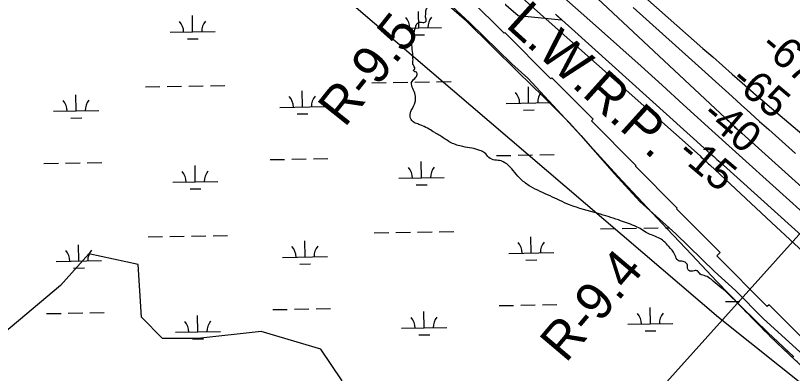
# Model space of a CAD drawing. Extents: x 3903937 to 3942190, y 260677 to 286651.
# Drawn here: x 3915846 to 3917570, y 282085 to 282879 of the extents above; entities that cross this region are included whole.
import ezdxf

# ---------------------------------------------------------------- set-up
doc = ezdxf.new("R2010")
doc.units = 0
for name, color, linetype in [('V-RIVR-EDGE', 7, 'Continuous'), ('V-RIVR-RANG', 7, 'Continuous'), ('V-RIVR-RANG-IDEN', 7, 'Continuous'), ('V-RRAP-FSHR', 7, 'Continuous'), ('V-RRAP-RVMT', 7, 'Continuous'), ('V-SITE-VEGE', 7, 'Continuous'), ('V-TOPO-DPTH', 7, 'Continuous'), ('V-TOPO-MAJR', 7, 'Continuous'), ('V-TOPO-MINR', 7, 'Continuous'), ('V-TOPO-WATR-IDEN', 7, 'Continuous'), ('V-WETL-SWMP', 7, 'Continuous')]:
    doc.layers.add(name, color=color, linetype=linetype)

msp = doc.modelspace()

# ---------------------------------------------------------------- linework, layer by layer
at = {"layer": 'V-RIVR-EDGE'}
for points in [[(3917425.1, 282263.8), (3917389, 282294.2), (3917376.9, 282301.5), (3917364.7, 282305.9), (3917358.9, 282312.7), (3917351.7, 282313.2), (3917339.5, 282313.8), (3917337.6, 282316.7), (3917335.7, 282327.9), (3917333.2, 282330.8), (3917324.5, 282334.2), (3917318.2, 282334.7), (3917313.8, 282338.1), (3917308, 282350.3), (3917295.5, 282366.8), (3917283.8, 282379), (3917272.2, 282386.3), (3917256.7, 282392.6), (3917245, 282398), (3917231.4, 282406.8), (3917219.3, 282412.6), (3917183.4, 282425.8), (3917138.3, 282440), (3917074.7, 282459.6), (3917032, 282479.1), (3916988.4, 282500.1), (3916967.5, 282515.7), (3916953.5, 282531.3), (3916939.4, 282546.9), (3916923.4, 282556.6), (3916909.4, 282558.6), (3916896.3, 282564), (3916886.6, 282574.7), (3916876.4, 282580.1), (3916858.4, 282585), (3916838.5, 282588.4), (3916812.3, 282597.2), (3916792, 282609.9), (3916782.3, 282615.7), (3916776, 282619.6), (3916763.8, 282627.4), (3916749.3, 282634.3), (3916741, 282637.7), (3916730.4, 282642.1), (3916723.6, 282648.4), (3916721.7, 282654.3), (3916721.7, 282661.1), (3916724.1, 282668.3), (3916732.9, 282687.7), (3916733.4, 282696), (3916730.5, 282710.6), (3916725.2, 282723.7), (3916724.8, 282730.5), (3916727.2, 282735.3), (3916735.5, 282744.1), (3916736.9, 282748.4), (3916736.5, 282752.3), (3916730.2, 282755.7), (3916729.2, 282758.2), (3916731.6, 282760.1), (3916731.6, 282763.5), (3916727.8, 282770.8), (3916727.3, 282772.7), (3916727.8, 282778.1), (3916727.8, 282783.9), (3916726.9, 282799), (3916725.5, 282818.4), (3916729.9, 282838.8), (3916731.4, 282846.1), (3916733.8, 282854.8), (3916737.7, 282862.1), (3916742.1, 282864.5), (3916751.8, 282863.5), (3916755.7, 282865.4), (3916757.2, 282868.8), (3916756.2, 282873.2), (3916756.2, 282883.9), (3916757.7, 282894.1), (3916764, 282902.3), (3916767, 282910.1), (3916770.4, 282913), (3916781, 282908.1), (3916789.3, 282907.6), (3916789.3, 282910), (3916782, 282918.8), (3916778.7, 282923.6), (3916763.6, 282935.3), (3916726.8, 282963.6), (3916714.2, 282972.9), (3916689, 282991.4), (3916632.3, 283034.2), (3916610, 283048.9), (3916578, 283066.9), (3916543, 283088.9), (3916510.1, 283112.7), (3916469.8, 283140.5), (3916444.2, 283160.5), (3916369, 283219), (3916281.3, 283284.2), (3916175.1, 283366.6), (3916089.8, 283429.9), (3915988, 283506.4), (3915917.7, 283560), (3915863.9, 283597.5), (3915811.6, 283639.9), (3915738.9, 283704.7)], [(3921377.3, 279062.2), (3921266.3, 279148.9), (3921205.7, 279194.7), (3921163, 279223.9), (3921117.5, 279259), (3921069, 279295.1), (3920989.5, 279356.5), (3920904.2, 279419.8), (3920848.5, 279465.1), (3920819.4, 279491.4), (3920764.6, 279532.3), (3920724.9, 279564.5), (3920717.6, 279574.2), (3920711.8, 279577.1), (3920707.9, 279580.1), (3920703.1, 279584.4), (3920697.7, 279590.3), (3920694.3, 279596.1), (3920679.8, 279608.3), (3920653.6, 279627.8), (3920647.8, 279633.1), (3920617.3, 279659.9), (3920603.2, 279669.7), (3920586.3, 279680.4), (3920572.2, 279685.8), (3920561.5, 279694.1), (3920554.7, 279695), (3920536.3, 279710.1), (3920503.8, 279735.5), (3920470.4, 279766.2), (3920409.9, 279826.5), (3920360.4, 279874.2), (3920304.2, 279925.9), (3920246.1, 279984.3), (3920184.1, 280042.2), (3920087.2, 280134.7), (3920077, 280142.5), (3920067.8, 280150.8), (3920023.2, 280189.8), (3919970.4, 280236), (3919916.1, 280284.7), (3919868.6, 280327.1), (3919856, 280338.3), (3919841, 280350), (3919835.2, 280353.4), (3919829.4, 280360.7), (3919822.1, 280368), (3919811.5, 280375.3), (3919804.7, 280378.7), (3919792.5, 280388), (3919779, 280401.1), (3919755.2, 280421.1), (3919718.9, 280448.4), (3919686.9, 280472.3), (3919581.7, 280567.7), (3919547.8, 280598.4), (3919513.9, 280625.2), (3919481.9, 280648.6), (3919448.9, 280669), (3919419.8, 280686.1), (3919392.7, 280705.6), (3919362.1, 280728), (3919330.2, 280752.9), (3919280.7, 280793.8), (3919246.8, 280820.1), (3919120.8, 280914.1), (3919044.2, 280969.7), (3918969, 281026.7), (3918955.5, 281036.9), (3918936.5, 281049.6), (3918911.8, 281069.6), (3918859, 281106.6), (3918831.8, 281126.6), (3918796, 281157.3), (3918776.6, 281169.5), (3918765, 281177.3), (3918749, 281193.3), (3918725.7, 281210.9), (3918705.3, 281225), (3918662.7, 281257.6), (3918621.5, 281285.9), (3918549.7, 281337.6), (3918525, 281357), (3918475.6, 281395.5), (3918463.5, 281407.2), (3918447, 281418.9), (3918411.1, 281449.1), (3918340.8, 281503.7), (3918290.9, 281544.1), (3918205.1, 281613.3), (3918154.7, 281655.7), (3918107.7, 281694.1), (3918054.9, 281736.5), (3917982.7, 281793), (3917905.1, 281852.5), (3917811.1, 281925.5), (3917735.9, 281981.1), (3917707.8, 282002.5), (3917656, 282043), (3917607.5, 282085.3), (3917579.9, 282111.1), (3917553.7, 282135.5), (3917491.7, 282196.3), (3917440.8, 282248.4), (3917425.1, 282263.8)]]:
    msp.add_spline(points, degree=3, dxfattribs=at)
at = {"layer": 'V-RIVR-RANG'}
msp.add_line((3917235.6, 282006.2), (3918051.2, 282913.5), dxfattribs=at)
at = {"layer": 'V-RRAP-FSHR'}
for points in [[(3917074.9, 282641.2), (3917017.9, 282698.1), (3916960.6, 282754), (3916903.8, 282810.2), (3916846.5, 282866.5), (3916786.6, 282919.1), (3916724.3, 282969.3), (3916659.5, 283016.2), (3916593.8, 283061.7), (3916528.8, 283108.4), (3916464, 283155.3), (3916399.2, 283202.2), (3916334.5, 283249.3), (3916270.4, 283297.1), (3916207.5, 283346.5), (3916144.8, 283396.3), (3916081.5, 283445.3), (3916016.3, 283491.4), (3915949.6, 283535.4), (3915885.9, 283583.8), (3915824.2, 283634.5)], [(3917572.9, 282122.4), (3917514.7, 282176.5), (3917457.4, 282232.6), (3917401.4, 282290.2), (3917346.3, 282348.2), (3917291.4, 282406.3), (3917236.8, 282464.7), (3917182.2, 282523.3), (3917128.2, 282582.3), (3917074.9, 282641.2)]]:
    msp.add_lwpolyline(points, dxfattribs=at)
at = {"layer": 'V-RRAP-RVMT'}
for p, q in [((3916930.3, 282839.7), (3916854.7, 282915.5)), ((3916931.9, 282841.3), (3916930.3, 282839.7)), ((3917033.9, 282738.7), (3916931.9, 282841.3)), ((3917036.1, 282740.9), (3917033.9, 282738.7)), ((3917127.4, 282649.1), (3917036.1, 282740.9)), ((3917123.8, 282645.6), (3917127.4, 282649.1)), ((3917222.7, 282546.2), (3917123.8, 282645.6)), ((3917221.6, 282545.1), (3917222.7, 282546.2)), ((3917314, 282452.2), (3917221.6, 282545.1)), ((3917312.7, 282450.8), (3917314, 282452.2)), ((3917409, 282353.9), (3917312.7, 282450.8)), ((3917401.5, 282346.3), (3917409, 282353.9)), ((3917513.5, 282233.6), (3917401.5, 282346.3)), ((3917517.7, 282237.8), (3917513.5, 282233.6)), ((3917617.1, 282137.8), (3917517.7, 282237.8))]:
    msp.add_line(p, q, dxfattribs=at)
at = {"layer": 'V-SITE-VEGE'}
for p, q in [((3916601.8, 282897), (3917405.5, 282210)), ((3916008.8, 282350.5), (3915946.3, 282280.2)), ((3916118, 282327.1), (3916008.8, 282350.5)), ((3916125.8, 282210), (3916118, 282327.1)), ((3915946.3, 282280.2), (3915805.9, 282163.1)), ((3916172.6, 282163.1), (3916125.8, 282210)), ((3917405.5, 282210), (3918685.2, 281187.3)), ((3916391.1, 282178.7), (3916250.6, 282163.1)), ((3916523.8, 282139.7), (3916391.1, 282178.7)), ((3916250.6, 282163.1), (3916172.6, 282163.1)), ((3916570.6, 282069.4), (3916523.8, 282139.7))]:
    msp.add_line(p, q, dxfattribs=at)
at = {"layer": 'V-TOPO-DPTH'}
for points in [[(3915796.4, 283808.7), (3915897.2, 283731), (3915998.4, 283653.8), (3916141.4, 283545.9), (3916171.5, 283523.1), (3916201.5, 283500.4), (3916231.6, 283477.6), (3916261.6, 283454.7), (3916269, 283449.1), (3916302.5, 283423.3), (3916335.9, 283397.3), (3916369, 283370.9), (3916401.9, 283344.3), (3916773.8, 283040.4), (3916800.9, 283018), (3916827.8, 282995.5), (3916854.4, 282972.6), (3916880.9, 282949.6), (3916960.8, 282879.2), (3917057.6, 282869.5)], [(3917615.2, 282422), (3917451.2, 282569.5), (3917435.9, 282583.2), (3917420.7, 282597), (3917405.6, 282610.7), (3917390.4, 282624.5), (3917327.4, 282682), (3917280.6, 282724.4), (3917233.8, 282766.7), (3917186.7, 282808.8), (3917139.6, 282850.9), (3916940.9, 283027.3)], [(3917615.2, 282422), (3917451.2, 282569.5), (3917435.9, 282583.2), (3917420.7, 282597), (3917405.6, 282610.7), (3917390.4, 282624.5), (3917327.4, 282682), (3917280.6, 282724.4), (3917233.8, 282766.7), (3917186.7, 282808.8), (3917139.6, 282850.9), (3916940.9, 283027.3)], [(3917080.1, 282971.1), (3917421.3, 282651.3), (3917424.8, 282647.9), (3917428.4, 282644.6), (3917432, 282641.2), (3917435.5, 282637.9), (3917440.7, 282633), (3917442.6, 282631.2), (3917446.3, 282627.8), (3917446.9, 282627.2), (3917450.1, 282624.4), (3917453.6, 282621.2), (3917457.1, 282618.1), (3917988, 282140.8)], [(3917988, 282140.8), (3917457.1, 282618.1), (3917453.6, 282621.2), (3917450.1, 282624.4), (3917446.9, 282627.2), (3917446.3, 282627.8), (3917442.6, 282631.2), (3917440.7, 282633), (3917435.5, 282637.9), (3917432, 282641.2), (3917428.4, 282644.6), (3917424.8, 282647.9), (3917421.3, 282651.3), (3917080.1, 282971.1)], [(3917057.6, 282869.5), (3917043.7, 282882)], [(3917043.7, 282882), (3917079.4, 282850), (3917380.7, 282579.1), (3917387.8, 282572.8), (3917394.9, 282566.4), (3917401.9, 282560), (3917409, 282553.7), (3917740.5, 282255.6)]]:
    msp.add_lwpolyline(points, dxfattribs=at)
at = {"layer": 'V-TOPO-MAJR'}
msp.add_lwpolyline([(3917216.3, 282896.6), (3917281.5, 282838.3), (3917346.5, 282779.8), (3917435.7, 282699.4), (3917456, 282681.1), (3917476.4, 282662.7), (3917496.8, 282644.4), (3917517.1, 282626.1), (3917576.3, 282572.9)], dxfattribs=at)
at = {"layer": 'V-TOPO-MINR'}
for points in [[(3917030.8, 283107.9), (3917371.1, 282806.3), (3917392.8, 282787.2), (3917414.4, 282768.1), (3917436.1, 282749.1), (3917457.8, 282730.1), (3917489, 282702.8), (3917495.1, 282697.5), (3917501.3, 282692.2), (3917507.5, 282686.9), (3917513.7, 282681.6), (3917906.9, 282348.9)], [(3916940.9, 283027.3), (3917139.6, 282850.9), (3917186.7, 282808.8), (3917233.8, 282766.7), (3917280.6, 282724.4), (3917327.4, 282682), (3917390.4, 282624.5), (3917405.6, 282610.7), (3917420.7, 282597), (3917435.9, 282583.2), (3917451.2, 282569.5), (3917615.2, 282422)], [(3916904.9, 282977.1), (3917364.6, 282567.7), (3917367.3, 282565.3), (3917370, 282562.8), (3917372.7, 282560.4), (3917375.3, 282558), (3917378, 282555.5), (3917380.7, 282553.1), (3917383.3, 282550.6), (3917386, 282548.2), (3917522.8, 282420.3), (3917594.1, 282354.2)], [(3917080.1, 282971.1), (3917421.3, 282651.3), (3917424.8, 282647.9), (3917428.4, 282644.6), (3917432, 282641.2), (3917435.5, 282637.9), (3917440.7, 282633), (3917442.6, 282631.2), (3917446.3, 282627.8), (3917446.9, 282627.2), (3917450.1, 282624.4), (3917453.6, 282621.2), (3917457.1, 282618.1), (3917988, 282140.8)], [(3917043.7, 282882), (3917079.4, 282850), (3917380.7, 282579.1), (3917387.8, 282572.8), (3917394.9, 282566.4), (3917401.9, 282560), (3917409, 282553.7), (3917740.5, 282255.6)]]:
    msp.add_lwpolyline(points, dxfattribs=at)
at = {"layer": 'V-WETL-SWMP'}
for p, q in [((3916794.7, 282918), (3916853.6, 282862.7)), ((3916239.1, 282842.9), (3916238.5, 282878.9)), ((3916741, 282851.8), (3916740.3, 282887.8)), ((3916853.6, 282862.7), (3916947.3, 282772.2)), ((3916189.1, 282842.1), (3916289.1, 282843.8)), ((3916691, 282850.9), (3916791, 282852.7)), ((3916227.4, 282827.3), (3916251.4, 282827.7)), ((3916729.2, 282836.1), (3916753.2, 282836.6)), ((3916947.3, 282772.2), (3916982.8, 282740.1)), ((3916982.8, 282740.1), (3917019.6, 282700.5)), ((3916134.4, 282721), (3916166.4, 282721.6)), ((3916182.4, 282721.9), (3916214.4, 282722.4)), ((3916230.4, 282722.7), (3916262.4, 282723.3)), ((3916278.4, 282723.5), (3916310.4, 282724.1)), ((3916636.3, 282729.8), (3916668.2, 282730.4)), ((3916684.2, 282730.7), (3916716.2, 282731.3)), ((3916732.2, 282731.5), (3916764.2, 282732.1)), ((3916780.2, 282732.4), (3916812.2, 282732.9)), ((3916984.4, 282685.2), (3916983.8, 282721.2)), ((3915980.7, 282667.6), (3915980.1, 282703.6)), ((3916482.6, 282676.4), (3916481.9, 282712.4)), ((3916934.4, 282684.3), (3917032.9, 282686.1)), ((3917019.6, 282700.5), (3917047.9, 282669.8)), ((3915930.8, 282666.7), (3916030.7, 282668.4)), ((3916432.6, 282675.5), (3916532.6, 282677.3)), ((3916972.7, 282669.6), (3916996.7, 282670)), ((3917047.9, 282669.8), (3917100.5, 282613.2)), ((3915969, 282651.9), (3915993, 282652.3)), ((3916470.9, 282660.8), (3916494.8, 282661.2)), ((3917100.5, 282613.2), (3917174.9, 282528.2)), ((3916913, 282568.5), (3916945, 282569.1)), ((3916961, 282569.4), (3916993, 282569.9)), ((3917009, 282570.2), (3917041, 282570.8)), ((3915909.4, 282550.9), (3915941.4, 282551.4)), ((3915957.4, 282551.7), (3915989.4, 282552.3)), ((3916005.4, 282552.5), (3916037.4, 282553.1)), ((3916245, 282510.3), (3916244.4, 282546.3)), ((3916411.2, 282559.7), (3916443.2, 282560.2)), ((3916459.2, 282560.5), (3916491.2, 282561.1)), ((3916507.2, 282561.4), (3916539.2, 282561.9)), ((3916746.8, 282519.2), (3916746.2, 282555.1)), ((3916696.8, 282518.3), (3916796.8, 282520)), ((3917174.9, 282528.2), (3917231.1, 282466.8)), ((3916195, 282509.4), (3916295, 282511.2)), ((3916233.3, 282494.7), (3916257.3, 282495.1)), ((3916735.1, 282503.5), (3916759.1, 282503.9)), ((3917231.1, 282466.8), (3917311.2, 282395.4)), ((3917239.9, 282407.7), (3917271.9, 282408.3)), ((3917287.9, 282408.6), (3917296.2, 282408.7)), ((3916284.3, 282390.9), (3916316.2, 282391.5)), ((3916642.1, 282397.2), (3916674.1, 282397.8)), ((3916690.1, 282398.1), (3916722.1, 282398.6)), ((3916738.1, 282398.9), (3916770.1, 282399.5)), ((3916786.1, 282399.8), (3916818.1, 282400.3)), ((3917143.9, 282406.1), (3917175.9, 282406.6)), ((3917191.9, 282406.9), (3917223.9, 282407.5)), ((3917311.2, 282395.4), (3917396.4, 282311.4)), ((3916140.3, 282388.4), (3916172.3, 282389)), ((3916188.3, 282389.2), (3916220.3, 282389.8)), ((3916236.3, 282390.1), (3916268.3, 282390.6)), ((3916488.4, 282343.8), (3916487.8, 282379.8)), ((3916990.3, 282352.6), (3916989.6, 282388.6)), ((3915986.6, 282334.9), (3915986, 282370.9)), ((3916438.4, 282342.9), (3916538.4, 282344.6)), ((3916940.3, 282351.7), (3917040.3, 282353.5)), ((3915936.6, 282334.1), (3916036.6, 282335.8)), ((3916476.7, 282328.1), (3916500.7, 282328.5)), ((3916978.5, 282337), (3917002.5, 282337.4)), ((3915974.9, 282319.3), (3915998.9, 282319.7)), ((3917396.4, 282311.4), (3917443.2, 282269.1)), ((3917443.2, 282269.1), (3917505, 282206.4)), ((3916918.9, 282235.9), (3916950.9, 282236.5)), ((3916966.9, 282236.7), (3916998.9, 282237.3)), ((3917014.9, 282237.6), (3917046.9, 282238.1)), ((3917420.7, 282244.7), (3917452.7, 282245.3)), ((3915915.2, 282218.2), (3915947.2, 282218.8)), ((3915963.2, 282219.1), (3915995.2, 282219.6)), ((3916011.2, 282219.9), (3916043.2, 282220.5)), ((3916417.1, 282227.1), (3916449.1, 282227.6)), ((3916465.1, 282227.9), (3916497.1, 282228.5)), ((3916513.1, 282228.8), (3916545, 282229.3)), ((3916752.7, 282186.5), (3916752, 282222.5)), ((3917254.5, 282195.4), (3917253.9, 282231.4)), ((3916250.8, 282177.7), (3916250.2, 282213.7)), ((3917505, 282206.4), (3917632, 282090.8)), ((3916702.7, 282185.7), (3916802.7, 282187.4)), ((3917204.5, 282194.5), (3917304.5, 282196.2)), ((3916200.9, 282176.8), (3916300.8, 282178.6)), ((3916740.9, 282170.9), (3916764.9, 282171.3)), ((3917242.8, 282179.7), (3917266.8, 282180.1)), ((3916239.1, 282162.1), (3916263.1, 282162.5))]:
    msp.add_line(p, q, dxfattribs=at)
for centre, start, end in [((3916685.7, 282851.3), 0.2366, 41.7802), ((3916796.2, 282853.2), 140.2366, 181.7802), ((3916183.9, 282842.4), 0.2366, 41.7802), ((3916294.4, 282844.4), 140.2366, 181.7802), ((3916929.2, 282684.7), 0.2366, 41.7802), ((3917039.6, 282686.7), 141.4788, 181.7802), ((3915925.5, 282667.1), 0.2366, 41.7802), ((3916036, 282669), 140.2366, 181.7802), ((3916427.3, 282675.9), 0.2366, 41.7802), ((3916537.8, 282677.8), 140.2366, 181.7802), ((3916189.7, 282509.8), 0.2366, 41.7802), ((3916300.2, 282511.8), 140.2366, 181.7802), ((3916691.6, 282518.7), 0.2366, 41.7802), ((3916802, 282520.6), 140.2366, 181.7802), ((3916935, 282352.1), 0.2366, 41.7802), ((3917045.5, 282354), 140.2366, 181.7802), ((3915931.4, 282334.4), 0.2366, 41.7802), ((3916041.8, 282336.4), 140.2366, 181.7802), ((3916433.2, 282343.3), 0.2366, 41.7802), ((3916543.7, 282345.2), 140.2366, 181.7802), ((3917309.7, 282196.8), 140.2366, 181.7802), ((3916306.1, 282179.1), 140.2366, 181.7802), ((3916697.4, 282186), 0.2366, 41.7802), ((3916807.9, 282188), 140.2366, 181.7802), ((3917199.3, 282194.9), 0.2366, 41.7802), ((3916195.6, 282177.2), 0.2366, 41.7802)]:
    msp.add_arc(centre, 35.2, start, end, dxfattribs=at)

# ---------------------------------------------------------------- texts
at = {"layer": 'V-RIVR-RANG'}
for s, p in [('-67', (3917494.6, 282805.9)), ('-65', (3917429.1, 282730.4)), ('-40', (3917365.1, 282653.6)), ('-15', (3917310.4, 282568.9))]:
    msp.add_text(s, height=67, rotation=319.9046, dxfattribs=at).set_placement(p)
at = {"layer": 'V-RIVR-RANG-IDEN'}
for s, rotation, p in [('R-9.5', 51.4221, (3916576.2, 282629.1)), ('R-9.4', 49.768, (3917066.8, 282107))]:
    msp.add_text(s, height=83, rotation=rotation, dxfattribs=at).set_placement(p)
at = {"layer": 'V-TOPO-WATR-IDEN'}
msp.add_text('L.W.R.P.', height=83, rotation=317.9407, dxfattribs=at).set_placement((3916931.3, 282855.5))

doc.saveas('drawing.dxf')
